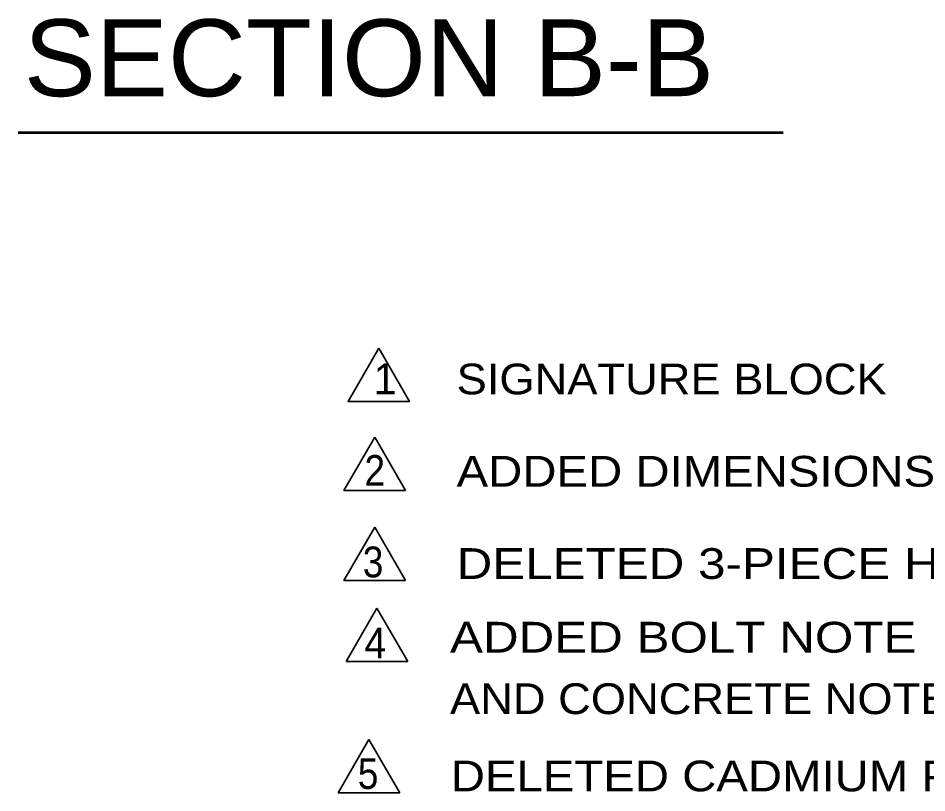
# Model space of a CAD drawing. Extents: x 442 to 1297, y -1132 to -588.
# Drawn here: x 1048.4 to 1119.2, y -993.4 to -933 of the extents above; entities that cross this region are included whole.
import ezdxf
from ezdxf.enums import TextEntityAlignment as Align

# ---------------------------------------------------------------- set-up
doc = ezdxf.new("R2010")
doc.units = 0
doc.header["$LTSCALE"] = 0.96
doc.layers.add('1', color=7, linetype='Continuous', lineweight=35)

msp = doc.modelspace()

# ---------------------------------------------------------------- linework, layer by layer
at = {"layer": '1', "lineweight": 53}
msp.add_line((1048.3605, -941.9173), (1108.0368, -941.9173), dxfattribs=at)
at = {"layer": '1'}
for p, q in [((1076.4865, -958.7328), (1078.8865, -962.8897)), ((1076.1705, -965.686), (1078.5705, -969.8429)), ((1076.1704, -972.7024), (1078.5704, -976.8593)), ((1076.3411, -979.0207), (1073.9411, -983.1776)), ((1076.3411, -979.0207), (1078.7411, -983.1776)), ((1073.9411, -983.1776), (1078.7411, -983.1776)), ((1075.7155, -989.2789), (1073.3155, -993.4358)), ((1075.7155, -989.2789), (1078.1155, -993.4358)), ((1073.3155, -993.4358), (1078.1155, -993.4358))]:
    msp.add_line(p, q, dxfattribs=at)
for points in [[(1076.4865, -958.7328), (1074.0865, -962.8897), (1078.8865, -962.8897)], [(1076.1705, -965.686), (1073.7705, -969.8429), (1078.5705, -969.8429)], [(1076.1704, -972.7024), (1073.7704, -976.8593), (1078.5704, -976.8593)]]:
    msp.add_lwpolyline(points, dxfattribs=at)

# ---------------------------------------------------------------- texts
for s, height, width, p in [('SECTION B-B', 6, 1.05, (1075.7169, -939.0789)), ('2', 2.4, 0.9, (1076.1706, -969.4776)), ('3', 2.4, 0.9, (1076.0441, -976.6204)), ('4', 2.4, 0.95, (1076.2148, -982.9387)), ('5', 2.4, 0.9, (1075.6542, -993.1319))]:
    msp.add_text(s, height=height, dxfattribs=dict(at, width=width)).set_placement(p, align=Align.CENTER)
msp.add_text('1', height=2.4, dxfattribs=at).set_placement((1076.977, -962.3348), align=Align.CENTER)
for s, width, p in [('SIGNATURE BLOCK', 1.1, (1082.5548, -962.3447)), ('ADDED DIMENSIONS ON BOLT-HOLE', 1.15, (1082.5548, -969.5447)), ('DELETED 3-PIECE H BOX', 1.2, (1082.5548, -976.7447)), ('ADDED BOLT NOTE FOR H, ADDED SCREW AND THICKNESS NOTE FOR L, ADDED CAST IRON NOTES', 1.2, (1082.0397, -982.4923)), ('AND CONCRETE NOTES', 1.1, (1082.0397, -987.2923)), ('DELETED CADMIUM PLATED BOLT', 1.15, (1082.0999, -993.3212))]:
    msp.add_text(s, height=2.4, dxfattribs=dict(at, width=width)).set_placement(p)

doc.saveas('drawing.dxf')
